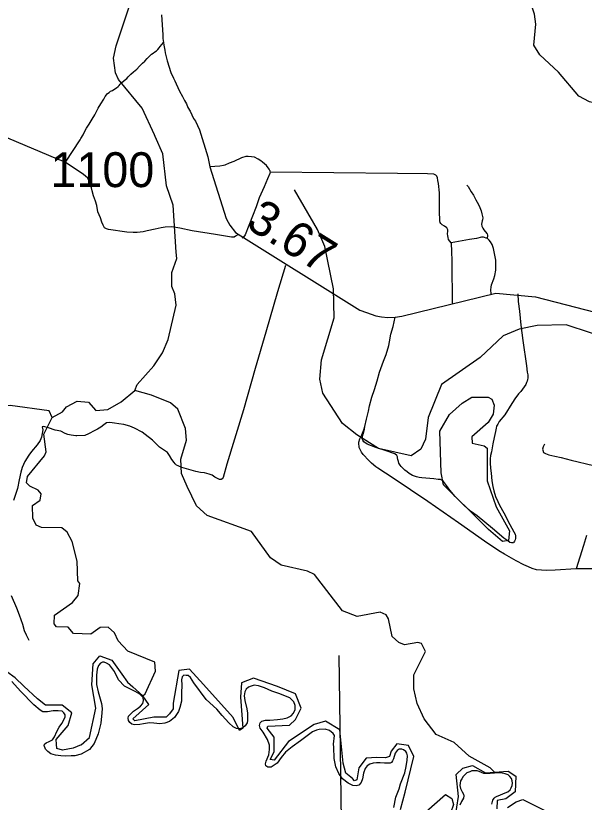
# Model space of a CAD drawing. Extents: x 2290615 to 2522933, y 819489 to 1012715.
# Drawn here: x 2414149 to 2422292, y 857856 to 869123 of the extents above; entities that cross this region are included whole.
import ezdxf

# ---------------------------------------------------------------- set-up
doc = ezdxf.new("R2010")
doc.units = 0
for name, color, linetype in [('Exist Boundary Political CountyLine', 7, 'Continuous'), ('Exist Hydrographic Misc Water Feature', 7, 'Continuous'), ('Exist Road Non-System Type 51', 7, 'Continuous'), ('Exist Road Secondary Mileage Hundredths English Label', 7, 'Continuous'), ('Exist Road Secondary Type 51 Attributed', 7, 'Continuous'), ('Exist Road Secondary Type 51 Number Label', 7, 'Continuous'), ('Map Preparation Longitude Latitude Lines', 7, 'Continuous')]:
    doc.layers.add(name, color=color, linetype=linetype)

msp = doc.modelspace()

# ---------------------------------------------------------------- linework, layer by layer
at = {"layer": 'Exist Boundary Political CountyLine'}
for points in [[(2416213, 858979), (2416125, 858988), (2416065, 858993), (2415979, 858979), (2415927, 858968), (2415850, 858963), (2415811, 858975), (2415782, 859000), (2415766, 859029), (2415761, 859059), (2415766, 859088), (2415793, 859118), (2415838, 859159), (2415893, 859197), (2415938, 859231), (2415970, 859272), (2415980, 859312), (2415976, 859355), (2415926, 859403), (2415860, 859444), (2415708, 859517), (2415622, 859610), (2415563, 859728), (2415490, 859823), (2415451, 859850), (2415417, 859864), (2415392, 859864), (2415361, 859848), (2415333, 859816), (2415317, 859764), (2415308, 859678), (2415308, 859544), (2415329, 859439), (2415376, 859271), (2415387, 859197), (2415384, 859136), (2415369, 858991), (2415330, 858836), (2415271, 858700), (2415205, 858614), (2415088, 858547), (2414995, 858519), (2414941, 858519), (2414866, 858517), (2414793, 858519), (2414720, 858533), (2414652, 858551), (2414607, 858583), (2414577, 858619), (2414554, 858668), (2414560, 858689), (2414585, 858709), (2414628, 858725), (2414674, 858752), (2414706, 858791), (2414740, 858870), (2414771, 858934), (2414808, 858986), (2414838, 859035), (2414857, 859078), (2414857, 859110), (2414838, 859139), (2414813, 859162), (2414757, 859167), (2414684, 859167), (2414605, 859151), (2414539, 859153), (2414499, 859177), (2414406, 859252), (2414216, 859447), (2414093, 859585)], [(2419484, 858416), (2419432, 858416), (2419369, 858423), (2419314, 858420), (2419269, 858414), (2419219, 858402), (2419180, 858380), (2419155, 858341), (2419130, 858271), (2419117, 858193), (2419098, 858139), (2419061, 858101), (2419027, 858092), (2418977, 858097), (2418911, 858129), (2418829, 858190), (2418775, 858269), (2418734, 858363), (2418709, 858481), (2418703, 858643), (2418700, 858687), (2418716, 858811), (2418696, 858841), (2418641, 858882), (2418583, 858905), (2418493, 858899), (2418457, 858889), (2418399, 858864), (2418306, 858793), (2418229, 858738), (2418108, 858652), (2418014, 858576), (2417949, 858497), (2417892, 858417), (2417835, 858376), (2417806, 858360), (2417762, 858360), (2417731, 858378), (2417728, 858406), (2417735, 858447), (2417774, 858537), (2417783, 858610), (2417783, 858674), (2417756, 858753), (2417692, 858858), (2417649, 858917), (2417640, 858955), (2417649, 858992), (2417676, 859017), (2417726, 859033), (2417790, 859033), (2417899, 859044), (2417976, 859049), (2418035, 859067), (2418092, 859094), (2418128, 859133), (2418151, 859183), (2418153, 859242), (2418132, 859296), (2418073, 859353), (2417915, 859412), (2417815, 859448), (2417712, 859494), (2417628, 859523), (2417565, 859532), (2417522, 859521), (2417481, 859507), (2417447, 859478), (2417429, 859437), (2417420, 859380), (2417429, 859312), (2417458, 859194), (2417467, 859133), (2417470, 859083), (2417470, 859026), (2417465, 858994), (2417436, 858951), (2417404, 858924), (2417361, 858908), (2417313, 858915), (2417263, 858937), (2417199, 858992), (2417104, 859101), (2417027, 859192), (2416875, 859330), (2416702, 859569), (2416650, 859641), (2416618, 859671), (2416589, 859673), (2416555, 859676), (2416532, 859653), (2416525, 859610), (2416530, 859539), (2416525, 859421), (2416521, 859303), (2416498, 859212), (2416478, 859158), (2416422, 859068), (2416349, 859011), (2416286, 858988), (2416213, 858979)], [(2419562, 857781), (2419594, 857931), (2419639, 858050), (2419660, 858122), (2419720, 858277), (2419743, 858366), (2419755, 858457), (2419759, 858520), (2419752, 858557), (2419734, 858584), (2419705, 858607), (2419680, 858616), (2419643, 858616), (2419611, 858598), (2419582, 858561), (2419559, 858480), (2419546, 858448), (2419530, 858427), (2419514, 858418), (2419484, 858416)], [(2420968, 857830), (2420982, 857885), (2420999, 857913), (2421017, 857930), (2421043, 857945), (2421083, 857959), (2421135, 857981), (2421197, 858007), (2421230, 858034), (2421247, 858061), (2421261, 858095), (2421262, 858130), (2421257, 858164), (2421249, 858195), (2421228, 858225), (2421201, 858247), (2421160, 858264), (2421118, 858273), (2421070, 858277), (2420946, 858267), (2420895, 858267), (2420854, 858268), (2420821, 858284), (2420787, 858296), (2420759, 858306), (2420717, 858306), (2420682, 858305), (2420652, 858294), (2420611, 858276), (2420585, 858255), (2420555, 858223), (2420538, 858194), (2420519, 858161), (2420513, 858130), (2420509, 858094), (2420517, 858055), (2420545, 858007), (2420562, 857973), (2420566, 857946), (2420560, 857916), (2420534, 857869), (2420508, 857816)]]:
    msp.add_lwpolyline(points, dxfattribs=at)
at = {"layer": 'Exist Hydrographic Misc Water Feature'}
msp.add_line((2416146, 867392), (2416135, 867417), dxfattribs=at)
for points in [[(2416135, 867417), (2415959, 867798), (2415619, 868211), (2415576, 868307), (2415548, 868516), (2415587, 868692), (2415915, 869687), (2415879, 869879), (2415303, 870463), (2415203, 870501), (2414786, 870497)], [(2424359, 867521), (2424332, 867535), (2423967, 867731), (2423405, 867932), (2422840, 867840), (2422582, 867836), (2422365, 867889), (2422213, 867972), (2421925, 868317), (2421655, 868562), (2421570, 868703), (2421599, 869003), (2421580, 869144), (2421519, 869328), (2421425, 869459), (2421232, 869566), (2421048, 869611)], [(2416445, 865736), (2416402, 866411), (2416306, 866686), (2416258, 867144), (2416146, 867392)], [(2422729, 864464), (2422034, 864695), (2421618, 864687), (2421360, 864634), (2421128, 864539), (2420800, 864227), (2420247, 863843), (2420054, 863366), (2420017, 863056), (2419952, 862915), (2419812, 862821), (2419344, 862923), (2419033, 863118), (2418831, 863280), (2418549, 863718), (2418505, 863917), (2418526, 864193), (2418709, 864795), (2418702, 865212), (2418577, 865820), (2418473, 866059), (2418140, 866630)], [(2415857, 863756), (2415890, 863839), (2416127, 864108), (2416250, 864294), (2416330, 864487), (2416448, 864978), (2416429, 865138), (2416386, 865245), (2416383, 865445), (2416455, 865645), (2416445, 865736)], [(2414672, 863369), (2414629, 863463), (2414069, 863538), (2413753, 863499), (2413464, 863353), (2413181, 863341), (2413005, 863380), (2412871, 863453), (2412727, 863585), (2412515, 863856), (2412351, 864213), (2412341, 864370), (2412265, 864436), (2411963, 864572), (2411878, 864670), (2411843, 864770), (2411841, 864954), (2411904, 865173), (2411907, 865548)], [(2414672, 863369), (2414821, 863448), (2414878, 863522), (2415027, 863600), (2415193, 863588), (2415295, 863470), (2415470, 863484), (2415660, 863593), (2415857, 863756)], [(2421006, 858286), (2420944, 858347), (2420641, 858515), (2420430, 858713), (2420170, 858828), (2420000, 859050), (2419897, 859273), (2419852, 859481), (2419849, 859681), (2420020, 860016), (2419959, 860132), (2419909, 860146), (2419718, 860112), (2419634, 860145), (2419541, 860233), (2419488, 860484), (2419454, 860541), (2419370, 860581), (2419037, 860518), (2418828, 860598), (2418429, 861117), (2418328, 861165), (2417952, 861251), (2417800, 861357), (2417528, 861736), (2416892, 861963), (2416740, 862101), (2416602, 862381), (2416525, 862565), (2416513, 862772), (2416593, 863041), (2416582, 863208), (2416470, 863489), (2416368, 863580), (2416092, 863690), (2415857, 863756)], [(2421121, 861591), (2420919, 861763), (2420276, 862404), (2420241, 862576), (2420224, 863170), (2420362, 863411), (2420543, 863573), (2420683, 863658), (2420916, 863661), (2420967, 863630), (2421001, 863546), (2420987, 863414), (2420913, 863296), (2420683, 863093), (2420684, 863001), (2420860, 862963), (2420902, 862928), (2420900, 862462), (2421031, 862090), (2421219, 861743), (2421205, 861608), (2421121, 861591)], [(2415970, 859379), (2416004, 859409), (2416149, 859733), (2416139, 859861), (2415754, 860019), (2415618, 860168), (2415566, 860284), (2415474, 860366), (2415357, 860358), (2415225, 860263), (2414975, 860276), (2414899, 860365), (2414732, 860371), (2414698, 860413), (2414705, 860538), (2414960, 860716), (2415042, 860817), (2415065, 860992), (2415039, 861027), (2415027, 861309), (2414956, 861592), (2414887, 861724), (2414811, 861789), (2414520, 861794), (2414444, 861827), (2414393, 861927), (2414390, 862107), (2414497, 862184), (2414513, 862276), (2414470, 862327), (2414353, 862384), (2414302, 862432), (2414317, 862524), (2414563, 862820), (2414587, 862877), (2414550, 863128), (2414672, 863369)], [(2415088, 858681), (2414974, 858632), (2414821, 858602), (2414737, 858627), (2414732, 858686), (2414730, 858756), (2414900, 858958), (2414954, 859136), (2414816, 859245), (2414574, 859245), (2414461, 859339), (2414263, 859518), (2414143, 859639), (2414023, 859723), (2413802, 859767), (2413705, 859791), (2413669, 859876), (2413645, 860189), (2413541, 860494), (2413392, 860675), (2413207, 860691), (2412963, 860655), (2412802, 860619)], [(2415088, 858681), (2415206, 858785), (2415295, 859203), (2415241, 859536), (2415258, 859840), (2415354, 859956), (2415525, 859890), (2415671, 859692), (2415752, 859576), (2415827, 859508), (2415970, 859379)], [(2419660, 857753), (2419725, 858000), (2419853, 858513), (2419774, 858667), (2419606, 858691), (2419527, 858588), (2419502, 858513), (2419443, 858494), (2419320, 858499), (2419169, 858486), (2419061, 858348), (2419036, 858175), (2419001, 858165), (2418972, 858195), (2418878, 858274), (2418838, 858417), (2418789, 858896), (2418586, 859020), (2418424, 858971), (2418058, 858728), (2417851, 858457), (2417791, 858467), (2417851, 858580), (2417851, 858788), (2417752, 858916), (2417762, 858946), (2418068, 858961), (2418157, 859040), (2418236, 859203), (2418157, 859410), (2417900, 859514), (2417554, 859633), (2417382, 859568), (2417367, 859361), (2417403, 858918), (2417353, 858886), (2417263, 859069), (2416836, 859541), (2416638, 859764), (2416485, 859744), (2416406, 859274), (2416406, 859195), (2416352, 859121), (2416303, 859077), (2416125, 859077), (2415853, 859022), (2415824, 859052), (2416056, 859255), (2415970, 859379)], [(2419675, 857664), (2419769, 857644), (2419883, 857678), (2419937, 857678), (2420026, 857723), (2420302, 857965), (2420396, 857911), (2420421, 857822), (2420332, 857575), (2420386, 857555), (2420441, 857634), (2420490, 857940), (2420456, 858252), (2420554, 858345), (2420693, 858385), (2420879, 858279), (2421006, 858286)], [(2421006, 858286), (2421202, 858302), (2421311, 858230), (2421303, 858006), (2421167, 857906), (2421044, 857879), (2421041, 857761)], [(2421190, 857779), (2421318, 857864), (2421410, 857896), (2421765, 857719)]]:
    msp.add_lwpolyline(points, dxfattribs=at)
at = {"layer": 'Exist Road Non-System Type 51'}
for points in [[(2414863, 867024), (2415070, 867345), (2415083, 867365), (2415115, 867416), (2415141, 867468), (2415163, 867513), (2415200, 867569), (2415244, 867641), (2415281, 867704), (2415331, 867797), (2415369, 867860), (2415409, 867929), (2415432, 867965), (2415448, 867988), (2415465, 868008), (2415485, 868025), (2415508, 868041), (2415535, 868054), (2415569, 868075), (2415593, 868092), (2415614, 868108), (2415629, 868124), (2415645, 868141), (2415662, 868160), (2415702, 868196), (2415740, 868223), (2415759, 868246), (2415797, 868284), (2415837, 868322), (2415884, 868360), (2415924, 868399), (2415966, 868444), (2415997, 868471), (2416033, 868511), (2416069, 868548), (2416095, 868572), (2416118, 868587), (2416143, 868604), (2416166, 868620), (2416182, 868639), (2416203, 868664), (2416220, 868682), (2416243, 868713), (2416265, 868741)], [(2414863, 867024), (2414747, 867070), (2414035, 867368), (2414014, 867385), (2413990, 867400), (2413967, 867415), (2413945, 867429), (2413922, 867438), (2413907, 867447), (2413887, 867462), (2413857, 867478), (2413822, 867496), (2413782, 867514), (2413726, 867536), (2413675, 867557), (2413605, 867586), (2413545, 867613), (2413512, 867631), (2413473, 867648), (2413454, 867655), (2413435, 867662)], [(2417795, 866882), (2417797, 866892), (2417789, 866904), (2417780, 866924), (2417742, 866976), (2417681, 867027), (2417661, 867044), (2417622, 867068), (2417570, 867095), (2417526, 867104), (2417476, 867108), (2417444, 867105), (2417384, 867086), (2417273, 867037), (2417207, 867010), (2417146, 866983), (2417124, 866979), (2417070, 866970), (2416930, 866960)], [(2417332, 865984), (2417298, 865965), (2417279, 865951), (2417269, 865949), (2417237, 865952), (2417010, 865989), (2416677, 866040), (2416501, 866080), (2416441, 866091), (2416381, 866100), (2416289, 866093), (2416233, 866086), (2416145, 866067), (2416032, 866043), (2415974, 866028), (2415890, 866017), (2415832, 866018), (2415738, 866024), (2415477, 866059), (2415448, 866071), (2415420, 866086), (2415400, 866125), (2415382, 866167), (2415361, 866230), (2415327, 866312), (2415310, 866406), (2415292, 866469), (2415265, 866543), (2415246, 866615), (2415233, 866657), (2415214, 866712), (2415203, 866745), (2415197, 866767), (2415177, 866800), (2415118, 866849), (2415029, 866912), (2414864, 867022), (2414863, 867024)], [(2417795, 866882), (2417789, 866862), (2417756, 866788), (2417708, 866673), (2417636, 866514), (2417594, 866387), (2417437, 865987), (2417411, 865952), (2417393, 865937)], [(2420385, 865868), (2420365, 865896), (2420348, 865920), (2420342, 865946), (2420340, 865970), (2420335, 866001), (2420337, 866036), (2420338, 866057), (2420334, 866067), (2420322, 866085), (2420292, 866107), (2420257, 866130), (2420237, 866148), (2420229, 866160), (2420225, 866184), (2420219, 866326), (2420217, 866586), (2420205, 866722), (2420196, 866765), (2420192, 866803), (2420179, 866823), (2420167, 866841), (2420137, 866856), (2420047, 866857), (2419619, 866865), (2417795, 866882)], [(2420609, 866697), (2420629, 866678), (2420673, 866602), (2420705, 866551), (2420738, 866487), (2420777, 866418), (2420798, 866374), (2420813, 866330), (2420827, 866285), (2420834, 866249), (2420838, 866227), (2420834, 866199), (2420830, 866185), (2420821, 866139), (2420826, 866111), (2420838, 866081), (2420852, 866055), (2420895, 866004), (2420899, 866000), (2420905, 865982), (2420906, 865970), (2420900, 865936)], [(2420900, 865936), (2420888, 865938), (2420864, 865945), (2420848, 865949), (2420822, 865949), (2420750, 865934), (2420646, 865918), (2420385, 865868)], [(2420956, 865141), (2420953, 865195), (2420956, 865233), (2420962, 865267), (2420997, 865355), (2421010, 865403), (2421025, 865480), (2421026, 865548), (2421025, 865620), (2421016, 865671), (2421003, 865741), (2420992, 865787), (2420971, 865845), (2420949, 865884), (2420929, 865910), (2420906, 865932), (2420900, 865936)], [(2420385, 865868), (2420386, 865842), (2420389, 865772), (2420393, 865588), (2420399, 865005)], [(2418015, 865546), (2417900, 865167), (2417730, 864589), (2417579, 864071), (2417411, 863480), (2417174, 862698), (2417119, 862507), (2417105, 862491), (2417092, 862481), (2417083, 862479), (2417069, 862480), (2417041, 862492), (2417002, 862512), (2416964, 862540), (2416918, 862558), (2416854, 862576), (2416794, 862581), (2416727, 862594), (2416530, 862653), (2416476, 862674), (2416451, 862685), (2416434, 862703), (2416416, 862724), (2416386, 862768), (2416350, 862822), (2416321, 862866), (2416279, 862894), (2416210, 862943), (2416106, 863042), (2416005, 863124), (2415959, 863158), (2415851, 863215), (2415785, 863243), (2415696, 863267), (2415626, 863279), (2415564, 863288), (2415499, 863295), (2415447, 863290), (2415409, 863265), (2415367, 863230), (2415321, 863199), (2415283, 863183), (2415193, 863135), (2415138, 863112), (2415023, 863104), (2415008, 863104), (2414945, 863114), (2414893, 863125), (2414859, 863140), (2414793, 863174), (2414715, 863188), (2414618, 863219), (2414545, 863237), (2414529, 863235), (2414535, 863190), (2414529, 863138), (2414516, 863088), (2414501, 863038), (2414454, 862976), (2414375, 862879), (2414339, 862829), (2414281, 862738), (2414242, 862654), (2414221, 862586), (2414197, 862476), (2414174, 862353), (2414119, 862181)], [(2421338, 865140), (2421343, 865030), (2421363, 864892), (2421385, 864692), (2421414, 864472), (2421465, 864110), (2421475, 864016), (2421485, 863978), (2421485, 863956), (2421484, 863933), (2421481, 863914), (2421475, 863890), (2421466, 863868), (2421455, 863839), (2421430, 863807), (2421382, 863741), (2421352, 863706), (2421325, 863674), (2421306, 863648), (2421256, 863568), (2421152, 863407), (2421075, 863309), (2421053, 863272), (2421037, 863242), (2421029, 863215), (2421020, 863167), (2421001, 863083), (2420982, 862990), (2420962, 862874), (2420949, 862823), (2420946, 862777), (2420943, 862715), (2420948, 862642), (2420957, 862571), (2420968, 862463), (2420982, 862379), (2420997, 862317), (2421022, 862238), (2421053, 862163), (2421080, 862111), (2421139, 862000), (2421228, 861837), (2421283, 861731), (2421300, 861697), (2421306, 861672), (2421306, 861655), (2421307, 861633), (2421303, 861616), (2421293, 861595), (2421283, 861581), (2421276, 861573), (2421266, 861573), (2421251, 861572), (2421226, 861579), (2421196, 861600), (2421140, 861639), (2420979, 861780), (2420760, 861957), (2420662, 862028), (2420526, 862153), (2420441, 862237), (2420365, 862329), (2420320, 862392), (2420288, 862434), (2420269, 862456), (2420252, 862471), (2420234, 862480), (2420197, 862481), (2420138, 862487), (2419965, 862506), (2419928, 862510), (2419891, 862520), (2419831, 862537), (2419783, 862564), (2419756, 862588), (2419723, 862613), (2419691, 862640), (2419671, 862665), (2419657, 862684), (2419638, 862715), (2419629, 862740), (2419621, 862766), (2419619, 862789), (2419615, 862805), (2419605, 862822), (2419577, 862847), (2419536, 862860), (2419483, 862879), (2419306, 862936), (2419180, 862986), (2419137, 863017), (2419119, 863041), (2419113, 863061), (2419111, 863075), (2419114, 863093), (2419123, 863129), (2419143, 863202), (2419150, 863237)], [(2422176, 861198), (2421877, 861183), (2421755, 861177), (2421677, 861182), (2421607, 861187), (2421547, 861204), (2421492, 861231), (2421426, 861258), (2421317, 861315), (2421148, 861408), (2421069, 861457), (2420863, 861594), (2420489, 861860), (2420051, 862164), (2419554, 862501), (2419336, 862640), (2419306, 862663), (2419245, 862716), (2419185, 862771), (2419142, 862821), (2419124, 862840), (2419101, 862872), (2419083, 862908), (2419070, 862936), (2419066, 862963), (2419065, 862983), (2419065, 863013), (2419078, 863062), (2419107, 863122), (2419134, 863190), (2419148, 863237), (2419150, 863237), (2419174, 863343), (2419200, 863459), (2419215, 863534), (2419248, 863658), (2419286, 863771), (2419324, 863891), (2419360, 864018), (2419416, 864174), (2419455, 864271), (2419491, 864401), (2419500, 864453), (2419522, 864562), (2419555, 864673), (2419583, 864805)], [(2421721, 862984), (2421705, 862950), (2421694, 862916), (2421696, 862902), (2421709, 862868), (2421737, 862854), (2421785, 862835), (2421871, 862812), (2421960, 862796), (2422102, 862758), (2422425, 862682)], [(2422326, 861679), (2422282, 861534), (2422176, 861198)], [(2422417, 861200), (2422176, 861198)], [(2414084, 860816), (2414159, 860642), (2414197, 860541), (2414246, 860407), (2414272, 860316), (2414300, 860255), (2414339, 860178)]]:
    msp.add_lwpolyline(points, dxfattribs=at)
at = {"layer": 'Exist Road Secondary Type 51 Attributed'}
msp.add_lwpolyline([(2416239, 869134), (2416258, 868849), (2416257, 868797), (2416265, 868741), (2416270, 868704), (2416283, 868629), (2416290, 868593), (2416318, 868478), (2416371, 868311), (2416407, 868230), (2416426, 868193), (2416445, 868148), (2416496, 868045), (2416539, 867968), (2416568, 867907), (2416594, 867859), (2416616, 867811), (2416646, 867756), (2416697, 867650), (2416722, 867613), (2416782, 867488), (2416902, 867100), (2416930, 866960), (2417165, 866221), (2417192, 866164), (2417214, 866124), (2417296, 866019), (2419079, 864906), (2419171, 864870), (2419307, 864825), (2419388, 864809), (2419480, 864801), (2419583, 864805), (2419677, 864818), (2421026, 865148), (2421592, 865098), (2422741, 864799)], dxfattribs=at)
at = {"layer": 'Map Preparation Longitude Latitude Lines'}
msp.add_line((2418880, 853121), (2418783, 859959), dxfattribs=at)

# ---------------------------------------------------------------- texts
at = {"layer": 'Exist Road Secondary Mileage Hundredths English Label'}
msp.add_text('3.67', height=500, rotation=328.0167, dxfattribs=at).set_placement((2417426, 866101))
at = {"layer": 'Exist Road Secondary Type 51 Number Label'}
msp.add_text('1100', height=500, rotation=360, dxfattribs=at).set_placement((2414646, 866668))

doc.saveas('drawing.dxf')
